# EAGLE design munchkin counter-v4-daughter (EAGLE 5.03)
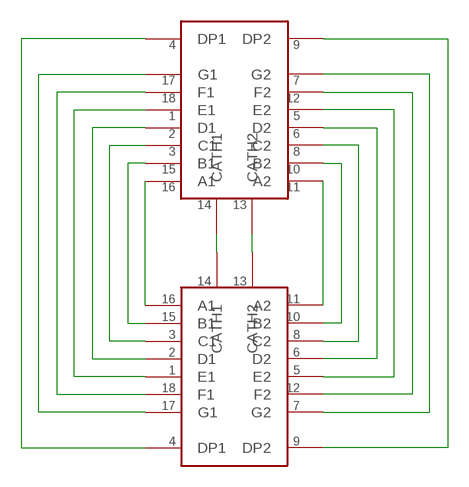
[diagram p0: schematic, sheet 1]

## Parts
U$2  DUAL7SEGMENTLED  [DUAL7-SEGMENTLED]
U$6  DUAL7SEGMENTLEDDUAL7SEGMENT-VIA-CABLE  [2X9HEADER]

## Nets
N$31: U$2.CATH2 U$6.P13/CATH2(CATH2)
N$32: U$2.CATH1 U$6.P14/CATH1(CATH1)
N$33: U$2.A2 U$6.P11/A2(A2)
N$34: U$2.B2 U$6.P10/B2(B2)
N$35: U$2.C2 U$6.P8/C2(C2)
N$36: U$2.D2 U$6.P6/D2(D2)
N$37: U$2.E2 U$6.P5/E2(E2)
N$38: U$2.F2 U$6.P12/F2(F2)
N$39: U$2.G2 U$6.P7/G2(G2)
N$40: U$2.DP2 U$6.P9/DP2(DP2)
N$41: U$2.A1 U$6.P16/A1(A1)
N$42: U$2.B1 U$6.P15/B1(B1)
N$43: U$2.C1 U$6.P3/C1(C1)
N$44: U$2.D1 U$6.P2/D2(D1)
N$45: U$2.E1 U$6.P1/E1(E1)
N$46: U$2.F1 U$6.P18/F1(F1)
N$47: U$2.G1 U$6.P17/G1(G1)
N$48: U$2.DP1 U$6.P4/DP1(DP1)

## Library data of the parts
U$2 U$6 = mkp:DUAL7SEGMENTLED: Dual 7 segment LED

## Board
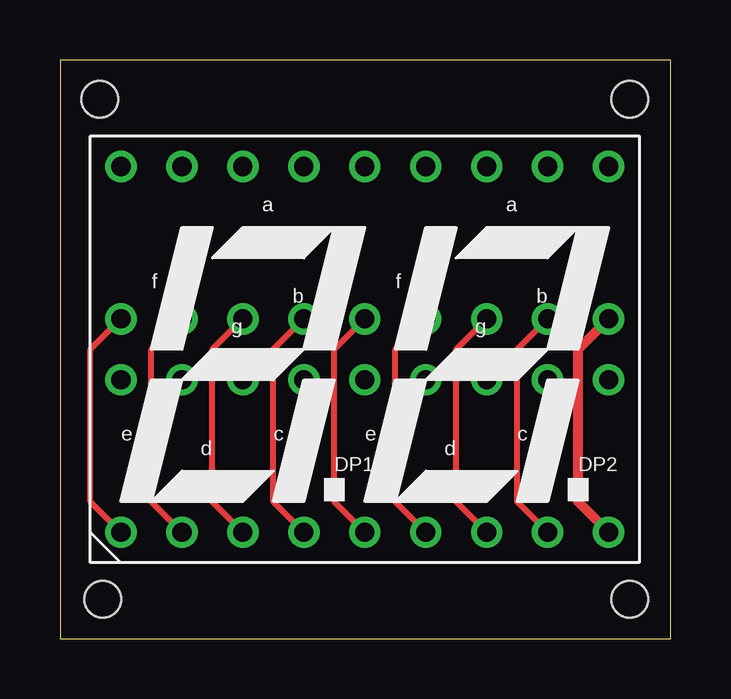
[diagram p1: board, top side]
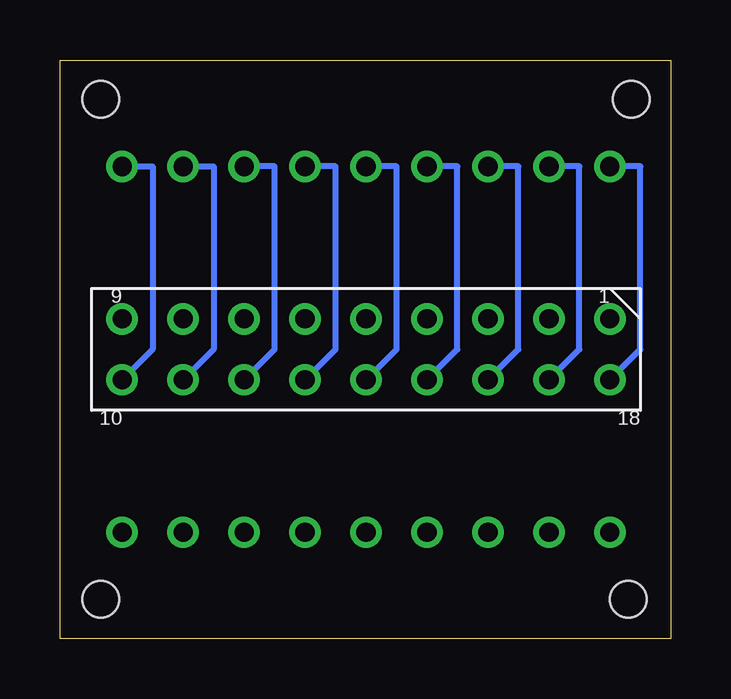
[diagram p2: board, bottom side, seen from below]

Size 25.45 x 24.12 mm. Coordinates in mm from the lower left corner, seen from the top.
Outline: 0,0 25.45,0 25.45,24.12 0,24.12 0,0
Copper layers (1*16): Top 0.035mm / dielectric 1.5mm / Bottom 0.035mm
Design rules "default": minimum track width 10mil, minimum drill 24mil, track to track 8mil, track to pad 8mil, pad to pad 8mil, via to via 8mil, smd to smd 8mil, copper to edge 40mil, drill to drill 8mil, minimum pad ring 10mil, minimum via ring 8mil, stop-mask expansion 4mil, vias tented up to drill 0mil, thermal gap 10mil
Holes 1.52 mm at 1.65,22.48 23.75,22.48 23.75,1.65 1.78,1.65

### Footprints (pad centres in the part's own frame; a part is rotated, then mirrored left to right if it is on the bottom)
DUAL7-SEGMENTLED = drill 0.8 round: A1 -5.08,7.62; A2 7.62,7.62; B1 -2.54,7.62; B2 10.16,7.62; C1 -5.08,-7.62; C2 7.62,-7.62; CATH1 0,7.62; CATH2 2.54,7.62; D1 -7.62,-7.62; D2 2.54,-7.62; DP1 -2.54,-7.62; DP2 10.16,-7.62; E1 -10.16,-7.62; E2 0,-7.62; F1 -10.16,7.62; F2 5.08,7.62; G1 -7.62,7.62; G2 5.08,-7.62
2X9HEADER = drill 0.8 round: P1/E1 -10.16,-1.27; P2/D2 -7.62,-1.27; P3/C1 -5.08,-1.27; P4/DP1 -2.54,-1.27; P5/E2 0,-1.27; P6/D2 2.54,-1.27; P7/G2 5.08,-1.27; P8/C2 7.62,-1.27; P9/DP2 10.16,-1.27; P10/B2 10.16,1.27; P11/A2 7.62,1.27; P12/F2 5.08,1.27; P13/CATH2 2.54,1.27; P14/CATH1 0,1.27; P15/B1 -2.54,1.27; P16/A1 -5.08,1.27; P17/G1 -7.62,1.27; P18/F1 -10.16,1.27

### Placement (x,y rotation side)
U$2  12.7,12.06 0 top
U$6  12.7,12.06 180 bottom

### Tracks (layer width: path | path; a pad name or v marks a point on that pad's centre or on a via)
N$31
  Bottom 0.254: U$6.P13/CATH2 13.97,12.06 13.97,19.68 U$2.CATH2
N$32
  Bottom 0.254: U$6.P14/CATH1 11.43,12.06 11.43,19.68 U$2.CATH1
N$33
  Bottom 0.254: U$2.A2 19.05,19.68 19.05,12.06 U$6.P11/A2
N$34
  Bottom 0.254: U$2.B2 21.59,19.68 21.59,12.06 U$6.P10/B2
N$35
  Top 0.254: U$2.C2 19.05,5.71 19.05,12.06 U$6.P8/C2
N$36
  Top 0.254: U$2.D2 13.97,5.71 13.97,12.06 U$6.P6/D2
N$37
  Top 0.254: U$2.E2 11.43,5.71 11.43,12.06 U$6.P5/E2
N$38
  Bottom 0.254: U$6.P12/F2 16.51,12.06 16.51,19.68 U$2.F2
N$39
  Top 0.254: U$2.G2 16.51,5.71 16.51,12.06 U$6.P7/G2
N$40
  Top 0.406: U$2.DP2 21.59,5.71 21.59,12.06 U$6.P9/DP2
N$41
  Bottom 0.254: U$6.P16/A1 6.35,12.06 6.35,19.68 U$2.A1
N$42
  Bottom 0.254: U$6.P15/B1 8.89,12.06 8.89,19.68 U$2.B1
N$43
  Top 0.254: U$2.C1 6.35,5.71 6.35,12.06 U$6.P3/C1
N$44
  Top 0.254: U$2.D1 3.81,5.71 3.81,12.06 U$6.P2/D2
N$45
  Top 0.254: U$2.E1 1.27,5.71 1.27,12.06 U$6.P1/E1
N$46
  Bottom 0.254: U$6.P18/F1 1.27,12.06 1.27,19.68 U$2.F1
N$47
  Bottom 0.254: U$6.P17/G1 3.81,12.06 3.81,19.68 U$2.G1
N$48
  Top 0.254: U$2.DP1 8.89,5.71 8.89,12.06 U$6.P4/DP1

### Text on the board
tDocu: Munchkin Counter | Daughter board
